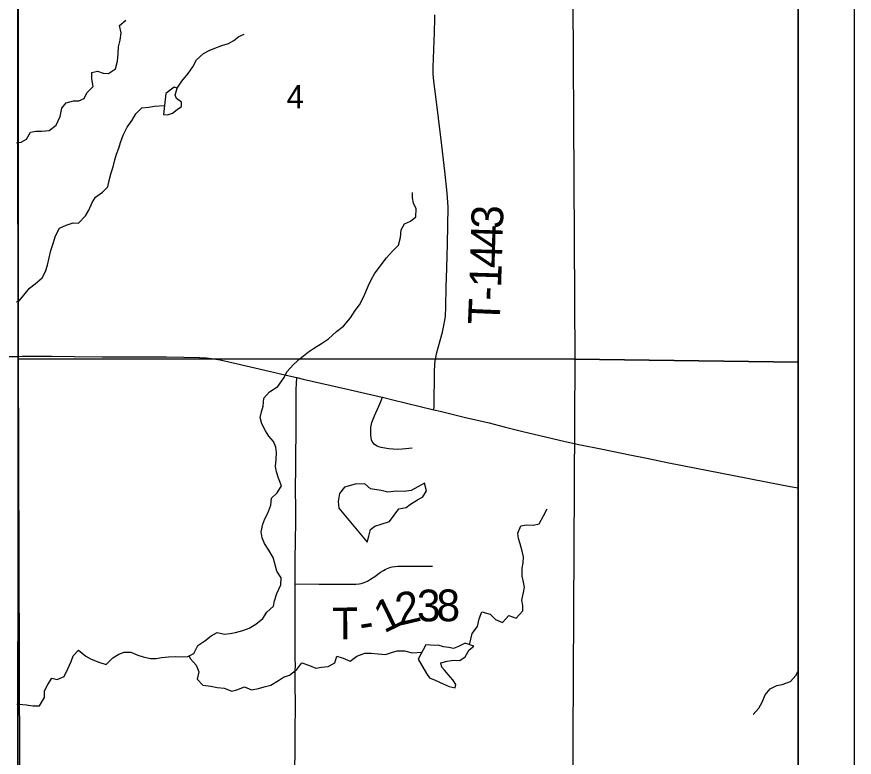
# Model space of a CAD drawing. Extents: x 0 to 34, y 0 to 22.
# Drawn here: x 7.503 to 9, y 16.591 to 17.915 of the extents above; entities that cross this region are included whole.
import ezdxf

# ---------------------------------------------------------------- set-up
doc = ezdxf.new("R2010")
doc.units = 0
for name, color, linetype in [('Default', 7, 'Continuous'), ('GM_X_Minor_Lake', 7, 'Continuous'), ('GM_X_Minor_River', 7, 'Continuous'), ('GM_X_Section', 7, 'Continuous'), ('GM_X_Section_Text', 7, 'Continuous'), ('GM_X_State_Route', 7, 'Continuous'), ('GM_X_Township_Road', 7, 'Continuous'), ('GM_X_Township_Road_Text', 7, 'Continuous'), ('SH_Cut_Line', 7, 'Continuous'), ('SH_Data', 7, 'Continuous')]:
    doc.layers.add(name, color=color, linetype=linetype)

msp = doc.modelspace()

# ---------------------------------------------------------------- linework, layer by layer
at = {"layer": 'Default'}
for points in [[(8.9, 14.1), (8.9, 18.2728)], [(7.5051, 18.039), (7.5053, 17.3084), (7.5076, 16.5733)], [(7.5076, 16.5733), (7.5053, 17.3084), (7.5051, 18.039)]]:
    msp.add_lwpolyline(points, dxfattribs=at)
for points in [[(8.9, 17.2976), (8.9, 18.2671), (8.4952, 18.2672), (8.5004, 17.303)], [(8.9, 16.282), (8.9, 17.2976), (8.5004, 17.303), (8.4953, 16.2856)]]:
    msp.add_lwpolyline(points, close=True, dxfattribs=at)
at = {"layer": 'GM_X_Minor_Lake'}
for points in [[(7.7649, 17.74), (7.7721, 17.7393), (7.7808, 17.7423), (7.7895, 17.7491), (7.7971, 17.7544), (7.7971, 17.762), (7.7884, 17.7685), (7.7861, 17.7749), (7.7895, 17.7871), (7.7839, 17.789), (7.7694, 17.7776)], [(7.7694, 17.7776), (7.7649, 17.74)], [(8.1293, 16.9756), (8.132, 16.9862), (8.135, 16.9984), (8.1426, 17.0044), (8.154, 17.0078), (8.1688, 17.0124), (8.1855, 17.0355), (8.1991, 17.0378), (8.2067, 17.0439), (8.2189, 17.0511), (8.2287, 17.0567), (8.2352, 17.0677), (8.2314, 17.081), (8.2079, 17.0678), (8.1954, 17.0662), (8.1817, 17.0666), (8.1658, 17.0651), (8.154, 17.0682), (8.1351, 17.0708), (8.1252, 17.0799), (8.1074, 17.0792), (8.0884, 17.0739), (8.0797, 17.0629), (8.077, 17.0481), (8.0785, 17.0367)], [(8.0785, 17.0367), (8.1293, 16.9756)], [(8.3041, 16.7953), (8.2923, 16.7892), (8.2836, 16.7858), (8.2752, 16.7873), (8.2654, 16.7888), (8.2559, 16.7915), (8.2487, 16.7911), (8.2426, 16.7919), (8.2339, 16.7923), (8.2202, 16.7665), (8.2354, 16.7407), (8.2407, 16.7331), (8.2506, 16.7289), (8.265, 16.7224), (8.2756, 16.7175), (8.2862, 16.7152), (8.2877, 16.7213), (8.282, 16.7296), (8.2737, 16.7391), (8.2673, 16.7467), (8.2627, 16.752), (8.2608, 16.76), (8.2722, 16.763), (8.2832, 16.7645), (8.295, 16.7642), (8.3044, 16.7706), (8.3113, 16.7831), (8.3196, 16.7896)], [(8.3196, 16.7896), (8.3041, 16.7953)]]:
    msp.add_lwpolyline(points, dxfattribs=at)
at = {"layer": 'GM_X_Minor_River'}
for points in [[(7.5023, 17.6895), (7.5102, 17.6906), (7.5202, 17.6958), (7.5271, 17.7087), (7.5365, 17.7106), (7.5472, 17.7105), (7.5604, 17.7117), (7.5733, 17.7208), (7.5802, 17.7363), (7.5832, 17.7515), (7.5908, 17.761), (7.6041, 17.7644), (7.6136, 17.7644), (7.623, 17.7689), (7.628, 17.7788), (7.6394, 17.7902), (7.6367, 17.8038), (7.6371, 17.8152), (7.647, 17.8175), (7.6568, 17.8141), (7.6667, 17.8133), (7.6792, 17.8216), (7.6826, 17.8357), (7.6838, 17.8486), (7.6845, 17.8611), (7.6872, 17.8732), (7.6895, 17.8861), (7.6864, 17.8991), (7.6974, 17.9085)], [(7.7895, 17.7871), (7.7979, 17.7996), (7.8089, 17.8132), (7.8176, 17.825), (7.8241, 17.8379), (7.8362, 17.8493), (7.8465, 17.8546), (7.8567, 17.8587), (7.8692, 17.8633), (7.881, 17.8667), (7.8905, 17.8724), (7.8999, 17.8796), (7.9094, 17.8837)], [(7.5023, 17.4052), (7.5071, 17.4069), (7.5152, 17.4173), (7.5254, 17.4294), (7.5357, 17.4374), (7.5478, 17.4483), (7.5539, 17.4597), (7.5573, 17.4707), (7.5603, 17.484), (7.5637, 17.4973), (7.5675, 17.5094), (7.5721, 17.5231), (7.5789, 17.5367), (7.5911, 17.5424), (7.6036, 17.5462), (7.6131, 17.5458), (7.6252, 17.5587), (7.6317, 17.5693), (7.6374, 17.5826), (7.6434, 17.5921), (7.6556, 17.6012), (7.6654, 17.6107), (7.6681, 17.6224), (7.6711, 17.6361), (7.6749, 17.6467), (7.678, 17.6589), (7.681, 17.6691), (7.6848, 17.6801), (7.6879, 17.69), (7.6928, 17.7033), (7.7, 17.7173), (7.7087, 17.7298), (7.7152, 17.7412), (7.7262, 17.7522), (7.7387, 17.7533), (7.7482, 17.7548), (7.7668, 17.756)], [(8.1743, 17.4958), (8.185, 17.5064), (8.1888, 17.5201), (8.1899, 17.5341), (8.196, 17.5447), (8.2066, 17.5497), (8.2161, 17.5572), (8.2165, 17.5717), (8.2119, 17.5815), (8.21, 17.591), (8.2104, 17.6005)], [(7.5026, 16.6864), (7.5065, 16.6864), (7.5201, 16.6849), (7.5311, 16.6834), (7.5432, 16.6834), (7.552, 16.6978), (7.5524, 16.7099), (7.5584, 16.7213), (7.5653, 16.7327), (7.5751, 16.7304), (7.5873, 16.7357), (7.5941, 16.7494), (7.5998, 16.7623), (7.6036, 16.7725), (7.6131, 16.7824), (7.626, 16.7721), (7.6354, 16.7664), (7.6495, 16.7611), (7.6627, 16.7573), (7.6745, 16.7691), (7.6851, 16.7755), (7.6946, 16.7793), (7.7068, 16.7789), (7.7189, 16.7736), (7.7284, 16.7709), (7.7416, 16.7679), (7.7519, 16.7679), (7.7621, 16.7694), (7.7739, 16.7709), (7.7864, 16.7713), (7.7985, 16.7705), (7.8084, 16.7713), (7.8194, 16.7769), (7.8262, 16.791), (7.8387, 16.7993), (7.8501, 16.808), (7.8607, 16.8145), (7.874, 16.8114), (7.8839, 16.8122), (7.8937, 16.8145), (7.907, 16.8179), (7.9184, 16.822), (7.9302, 16.8292), (7.9423, 16.8391), (7.9499, 16.8505), (7.9616, 16.8615), (7.9632, 16.871), (7.9677, 16.8842), (7.9749, 16.8994), (7.9753, 16.9119), (7.9674, 16.9241), (7.9643, 16.9374), (7.9609, 16.9484), (7.9533, 16.9613), (7.9458, 16.9731), (7.9412, 16.9837), (7.9397, 16.9943), (7.9428, 17.008), (7.9462, 17.0174), (7.9515, 17.0277), (7.9568, 17.0417), (7.9583, 17.0546), (7.9682, 17.0637), (7.9758, 17.0762), (7.9705, 17.0899), (7.9667, 17.1013), (7.9652, 17.1112), (7.9663, 17.1233), (7.9671, 17.1358), (7.966, 17.1453), (7.9614, 17.1556), (7.9535, 17.1654), (7.9474, 17.1749), (7.9406, 17.1871), (7.9379, 17.1984), (7.9402, 17.2087), (7.9432, 17.2186), (7.9444, 17.2333), (7.9546, 17.2443), (7.9694, 17.2538), (7.9808, 17.2701), (7.9857, 17.2804), (7.9975, 17.2933), (8.0093, 17.3039), (8.0244, 17.316), (8.0351, 17.3232), (8.0476, 17.3308), (8.0597, 17.3391), (8.0741, 17.3524), (8.0867, 17.3619), (8.0992, 17.3767), (8.1079, 17.3896), (8.1151, 17.4002), (8.1223, 17.4135), (8.1265, 17.4233), (8.1311, 17.4332), (8.1371, 17.4457), (8.1421, 17.4556), (8.1523, 17.4692), (8.1637, 17.484), (8.1743, 17.4958)], [(8.3123, 16.7922), (8.317, 16.8127), (8.3261, 16.8252), (8.3291, 16.8385), (8.3344, 16.8514), (8.3488, 16.8468), (8.3587, 16.8377), (8.3708, 16.8324), (8.3822, 16.8445), (8.3955, 16.84), (8.4073, 16.8529), (8.4076, 16.8624), (8.4054, 16.8718), (8.4088, 16.8855), (8.4107, 16.895), (8.4084, 16.9045), (8.4061, 16.9151), (8.4062, 16.9291), (8.4081, 16.939), (8.4084, 16.9496), (8.4065, 16.9595), (8.4028, 16.9728), (8.3994, 16.9823), (8.3986, 16.9918), (8.4039, 17.0047), (8.4138, 17.0065), (8.4267, 17.0058), (8.4365, 17.0084), (8.4445, 17.0228), (8.451, 17.0354)], [(7.8104, 16.7723), (7.8133, 16.7671), (7.8232, 16.7561), (7.8281, 16.7439), (7.8251, 16.731), (7.8353, 16.7204), (7.8493, 16.7181), (7.8607, 16.7162), (7.8736, 16.7147), (7.8869, 16.7094), (7.8963, 16.712), (7.9096, 16.7173), (7.9225, 16.712), (7.935, 16.7143), (7.9449, 16.7169), (7.9566, 16.72), (7.9703, 16.7287), (7.9798, 16.7344), (7.99, 16.7378), (8.0033, 16.7484), (8.012, 16.7601), (8.0261, 16.7552), (8.0371, 16.7503), (8.0473, 16.7522), (8.0594, 16.7537), (8.0712, 16.7601), (8.0746, 16.7719), (8.0864, 16.7684), (8.0985, 16.7631), (8.1106, 16.7722), (8.1251, 16.7775), (8.1361, 16.7775), (8.1486, 16.776), (8.1618, 16.7752), (8.1725, 16.7786), (8.1827, 16.7817), (8.196, 16.7817), (8.2096, 16.7782), (8.2268, 16.7789)], [(8.8194, 16.6678), (8.8293, 16.6792), (8.8353, 16.6895), (8.841, 16.7027), (8.8494, 16.7137), (8.8615, 16.7194), (8.8714, 16.7213), (8.8862, 16.7266), (8.8957, 16.7376), (8.9, 16.7449)]]:
    msp.add_lwpolyline(points, dxfattribs=at)
at = {"layer": 'GM_X_Section'}
for points in [[(8.4952, 18.2672), (8.5004, 17.303), (7.5048, 17.3031), (7.5042, 18.265)], [(7.5048, 17.3031), (8.5004, 17.303), (8.4953, 16.2856), (7.5047, 16.2943)]]:
    msp.add_lwpolyline(points, close=True, dxfattribs=at)
at = {"layer": 'GM_X_State_Route'}
for points in [[(6.9808, 17.3035), (6.9838, 17.3036), (7.0155, 17.304), (7.0899, 17.3042), (7.1396, 17.3038), (7.1706, 17.3039), (7.2109, 17.3042), (7.245, 17.3044), (7.2666, 17.3044), (7.2853, 17.3044), (7.3101, 17.3047), (7.3318, 17.3051), (7.3504, 17.3054), (7.369, 17.3057), (7.4247, 17.3071), (7.4743, 17.3076), (7.4973, 17.3078), (7.5055, 17.3078)], [(7.5055, 17.3078), (7.5123, 17.3079), (7.5651, 17.3079), (7.6055, 17.3078), (7.6552, 17.3071), (7.6801, 17.307), (7.7702, 17.3068), (7.8013, 17.3066), (7.8292, 17.306), (7.8416, 17.3052), (7.8508, 17.3041), (7.8661, 17.3015), (7.8873, 17.297), (7.9206, 17.2891), (7.9538, 17.2813), (7.9841, 17.2741), (8.0033, 17.2698), (8.0147, 17.2673), (8.0962, 17.2486), (8.1507, 17.236), (8.1566, 17.2346), (8.1749, 17.2302), (8.2485, 17.2123), (8.2594, 17.2097), (8.3047, 17.1985), (8.3471, 17.1887), (8.3742, 17.1818), (8.4074, 17.1737), (8.4376, 17.1665), (8.483, 17.1557), (8.5073, 17.1504), (8.5499, 17.1417), (8.5987, 17.132), (8.6291, 17.1257), (8.6687, 17.1177), (8.7846, 17.0947), (8.8425, 17.0833), (8.8853, 17.0751), (8.9, 17.0726)]]:
    msp.add_lwpolyline(points, dxfattribs=at)
at = {"layer": 'GM_X_Township_Road'}
for points in [[(8.2485, 17.2123), (8.2486, 17.2188), (8.2497, 17.281), (8.2502, 17.2935), (8.2508, 17.2996), (8.2518, 17.3058), (8.2539, 17.3149), (8.2596, 17.3359), (8.2635, 17.3509), (8.2662, 17.3631), (8.268, 17.3722), (8.269, 17.3789), (8.2696, 17.3971), (8.2703, 17.4313), (8.2715, 17.4654), (8.2725, 17.509), (8.2739, 17.5743), (8.2734, 17.5836), (8.2719, 17.5992), (8.2681, 17.639), (8.2614, 17.6949), (8.2518, 17.7721), (8.2481, 17.7998), (8.2471, 17.8129), (8.2469, 17.8248), (8.2475, 17.8403), (8.2494, 17.8869), (8.2502, 17.9118), (8.2502, 17.918)], [(8.0006, 16.9011), (8.0006, 16.9151), (8.0005, 16.9471), (8.0008, 16.9751), (8.0013, 17.0156), (8.0014, 17.0312), (8.0012, 17.0748), (8.0014, 17.106), (8.0016, 17.134), (8.002, 17.1683), (8.002, 17.1901), (8.0023, 17.2493), (8.0027, 17.2587), (8.0033, 17.2698)], [(8.2095, 17.1438), (8.1918, 17.1422), (8.184, 17.1416), (8.1755, 17.1419), (8.1681, 17.1426), (8.1606, 17.1438), (8.154, 17.1449), (8.1499, 17.146), (8.147, 17.1473), (8.1441, 17.1488), (8.1417, 17.1508), (8.1397, 17.1532), (8.1381, 17.1559), (8.1371, 17.1588), (8.1364, 17.1619), (8.1356, 17.1681), (8.1355, 17.1743), (8.1358, 17.1806), (8.1368, 17.1867), (8.1376, 17.1898), (8.1386, 17.1927), (8.1421, 17.2015), (8.1497, 17.2186), (8.1534, 17.2272), (8.1566, 17.2346)], [(8.0006, 16.9011), (8.0432, 16.9008), (8.0745, 16.9007), (8.0963, 16.9004), (8.1088, 16.9006), (8.115, 16.9012), (8.1181, 16.9018), (8.124, 16.9038), (8.1298, 16.9062), (8.1352, 16.9093), (8.143, 16.9146), (8.1531, 16.9219), (8.1584, 16.9253), (8.1611, 16.9268), (8.1639, 16.9281), (8.1668, 16.9293), (8.1697, 16.9304), (8.174, 16.9315), (8.1792, 16.9323), (8.1839, 16.9327), (8.1915, 16.9327), (8.2353, 16.9329), (8.2462, 16.933)], [(7.9999, 16.5689), (8.0002, 16.603), (8.0006, 16.6403), (8.0009, 16.6806), (8.0008, 16.693), (8.0006, 16.7147), (8.0005, 16.7333), (8.0005, 16.7458), (8.0007, 16.7551), (8.0004, 16.7675), (8.0006, 16.7737), (8.0006, 16.7768), (8.0002, 16.7892), (8.0001, 16.8109), (8.0005, 16.8389), (8.0006, 16.8979), (8.0006, 16.9011)]]:
    msp.add_lwpolyline(points, dxfattribs=at)
at = {"layer": 'SH_Cut_Line'}
for points in [[(8.9, 14.1), (8.9, 20.9)], [(7.5076, 16.5733), (7.5053, 17.3084), (7.5051, 18.039)], [(7.5051, 18.039), (7.5053, 17.3084), (7.5076, 16.5733)]]:
    msp.add_lwpolyline(points, dxfattribs=at)
at = {"layer": 'SH_Data'}
for p, q in [((9, 21), (9, 14)), ((8.9, 20.9), (8.9, 14.1))]:
    msp.add_line(p, q, dxfattribs=at)

# ---------------------------------------------------------------- texts
at = {"layer": 'GM_X_Section_Text'}
msp.add_text('4', height=0.0419, rotation=0, dxfattribs=at).set_placement((7.985, 17.751))
at = {"layer": 'GM_X_Township_Road_Text'}
for s, rotation, p in [('3', 88.2609, (8.3717, 17.535)), ('4', 88.2575, (8.3706, 17.5)), ('4', 88.2506, (8.3696, 17.465)), ('1', 88.2229, (8.3685, 17.43)), ('-', 88.1323, (8.3677, 17.4066)), ('T', 87.5951, (8.3659, 17.3636)), ('3', 0.3331, (8.2182, 16.834)), ('8', 0.3856, (8.2532, 16.8342)), ('2', 13.231, (8.1874, 16.8264)), ('1', 25.9225, (8.1591, 16.8122)), ('T', 0.2829, (8.0668, 16.802)), ('-', 9.2702, (8.119, 16.803))]:
    msp.add_text(s, height=0.0568, rotation=rotation, dxfattribs=at).set_placement(p)

doc.saveas('drawing.dxf')
